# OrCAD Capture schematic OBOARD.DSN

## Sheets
1 core: size B
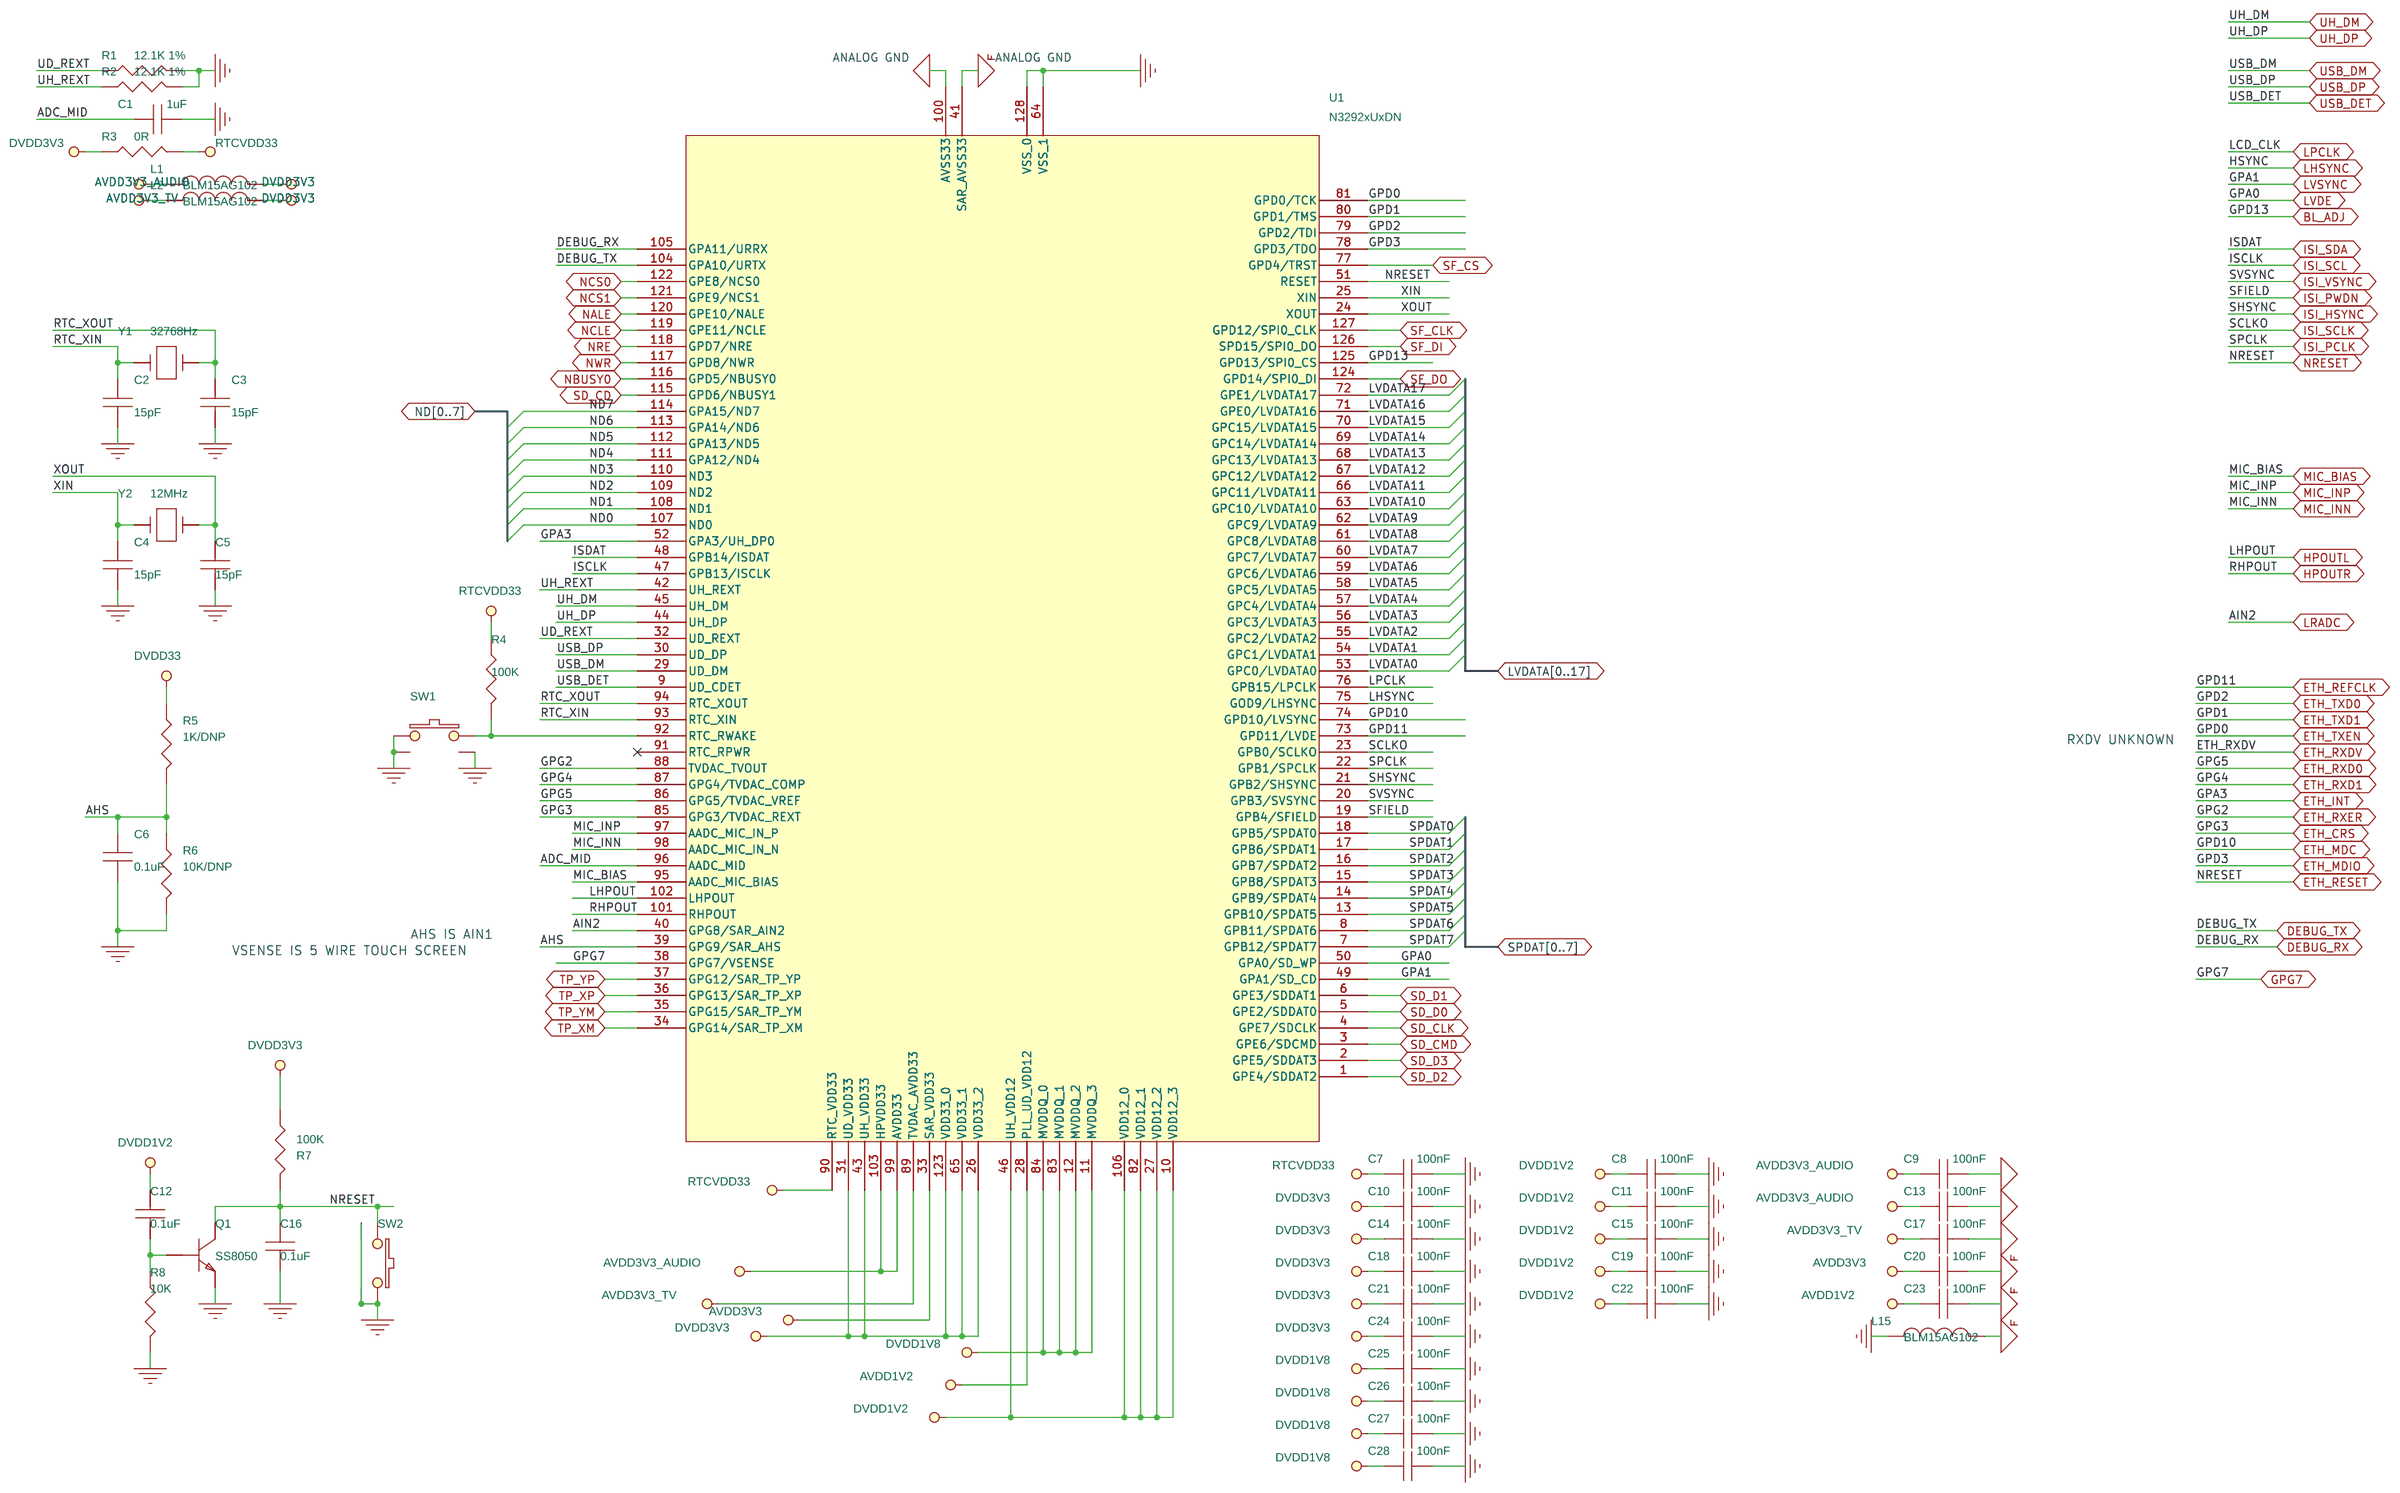
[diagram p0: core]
2 flash: size A
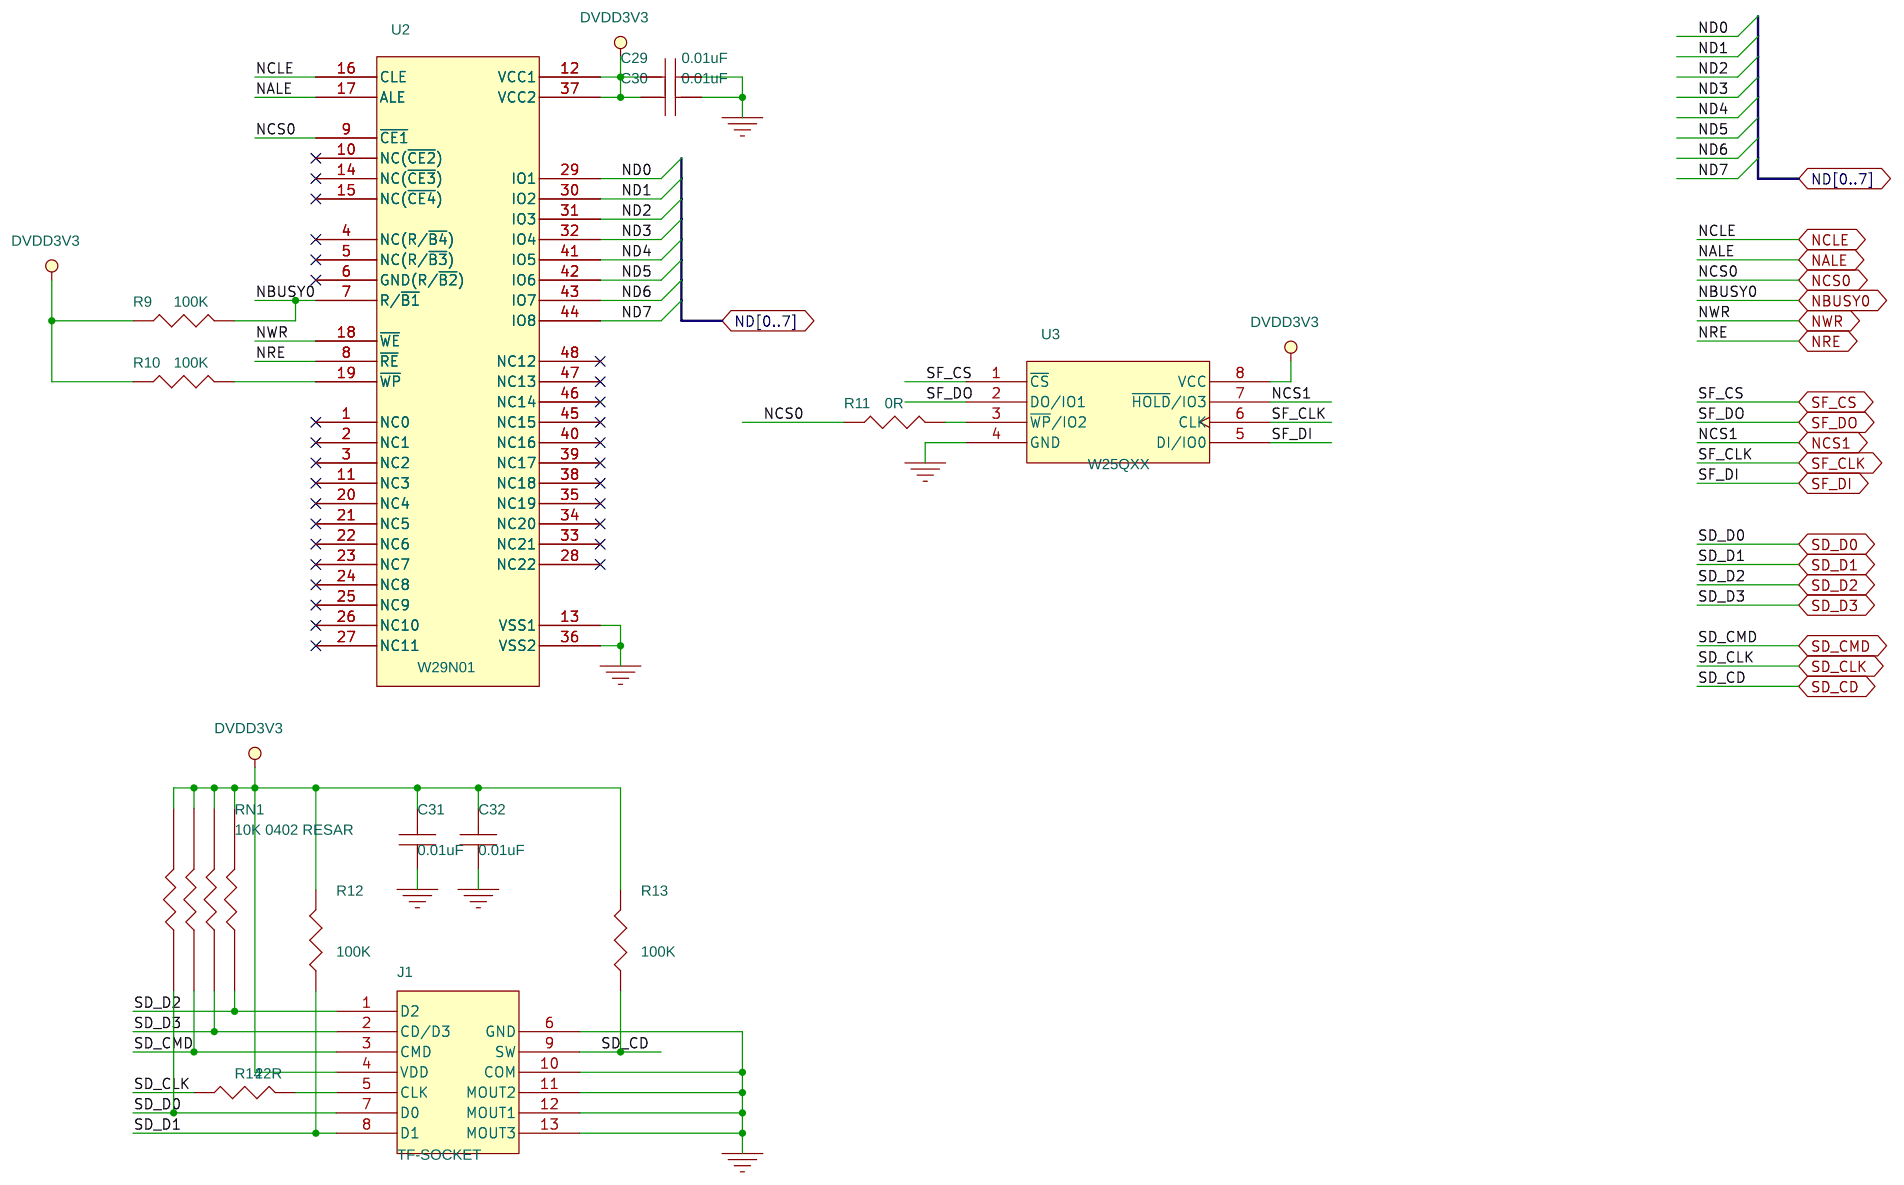
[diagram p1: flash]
3 lcd&isi: size A
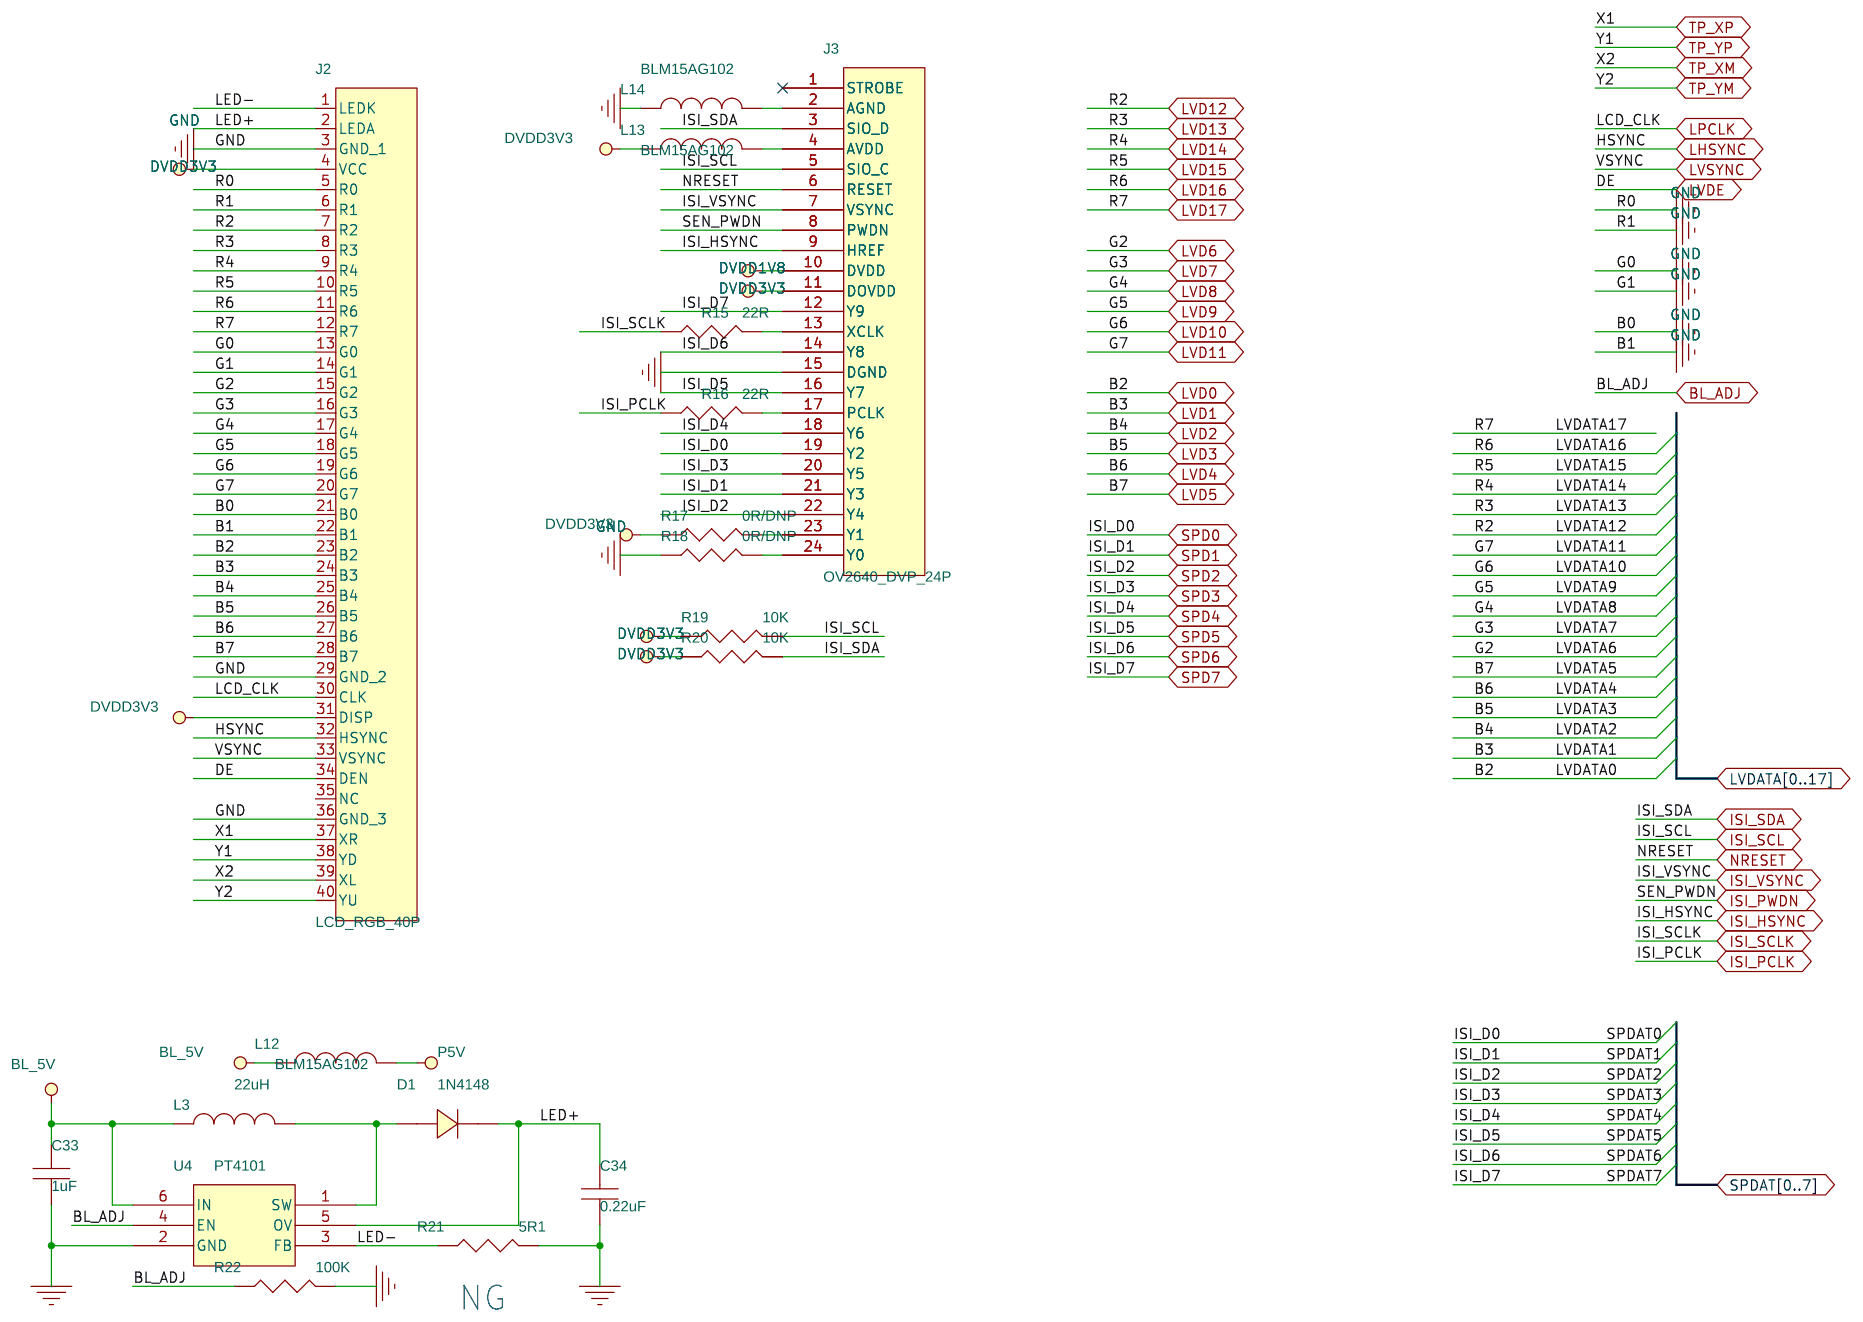
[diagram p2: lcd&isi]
4 misc: size A
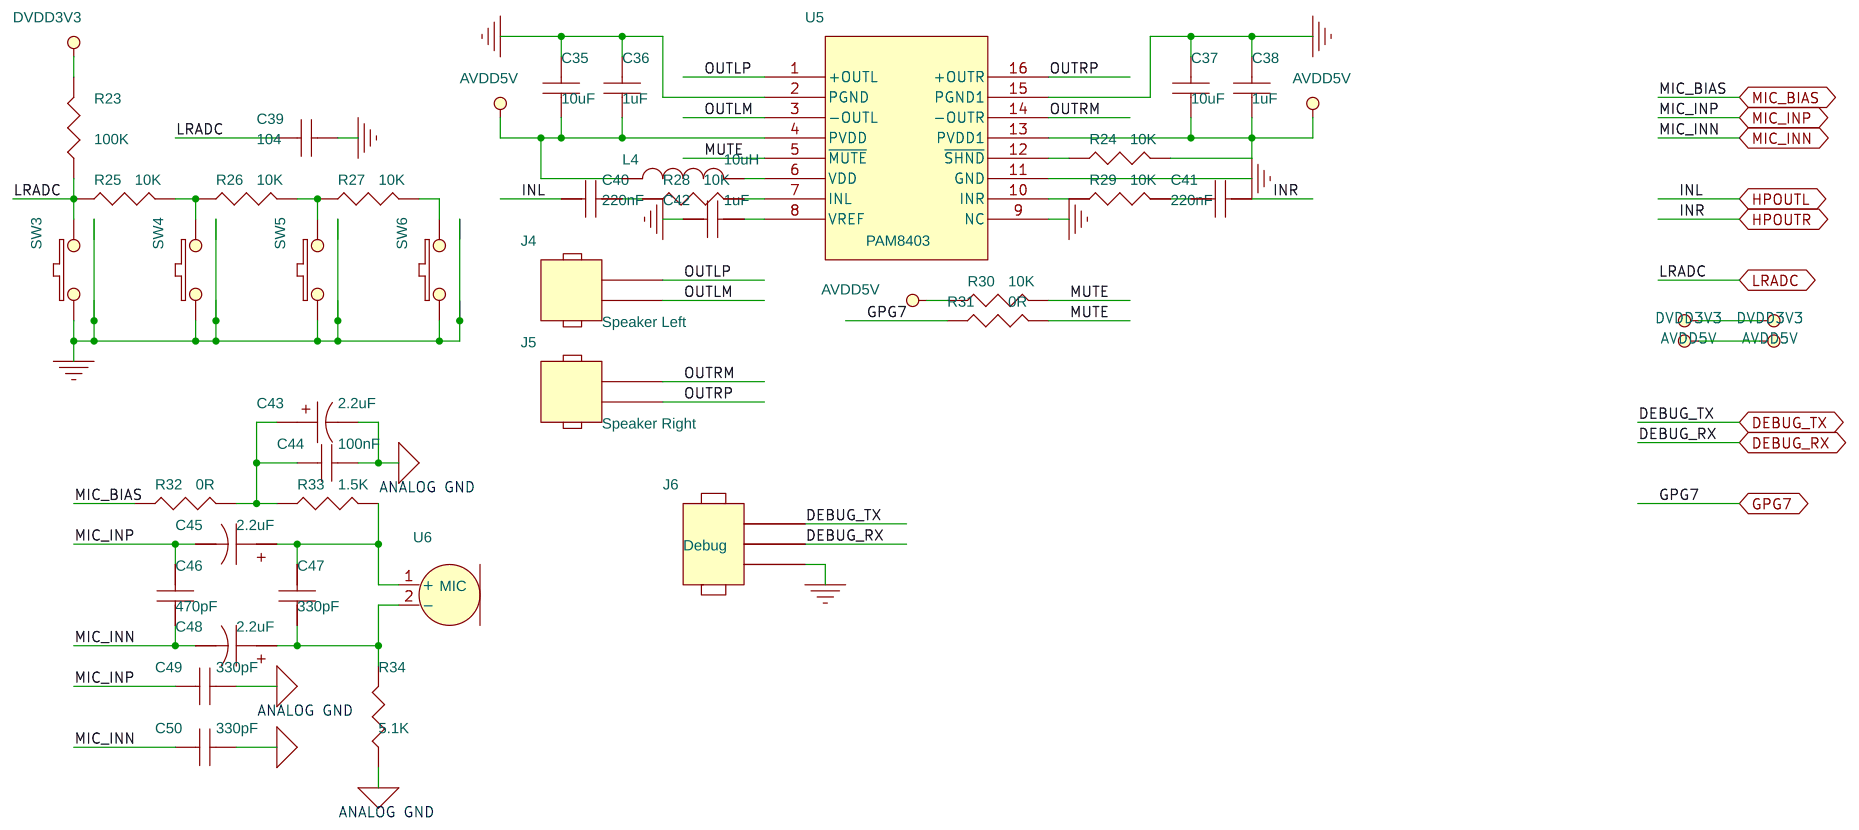
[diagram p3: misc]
5 net: size A
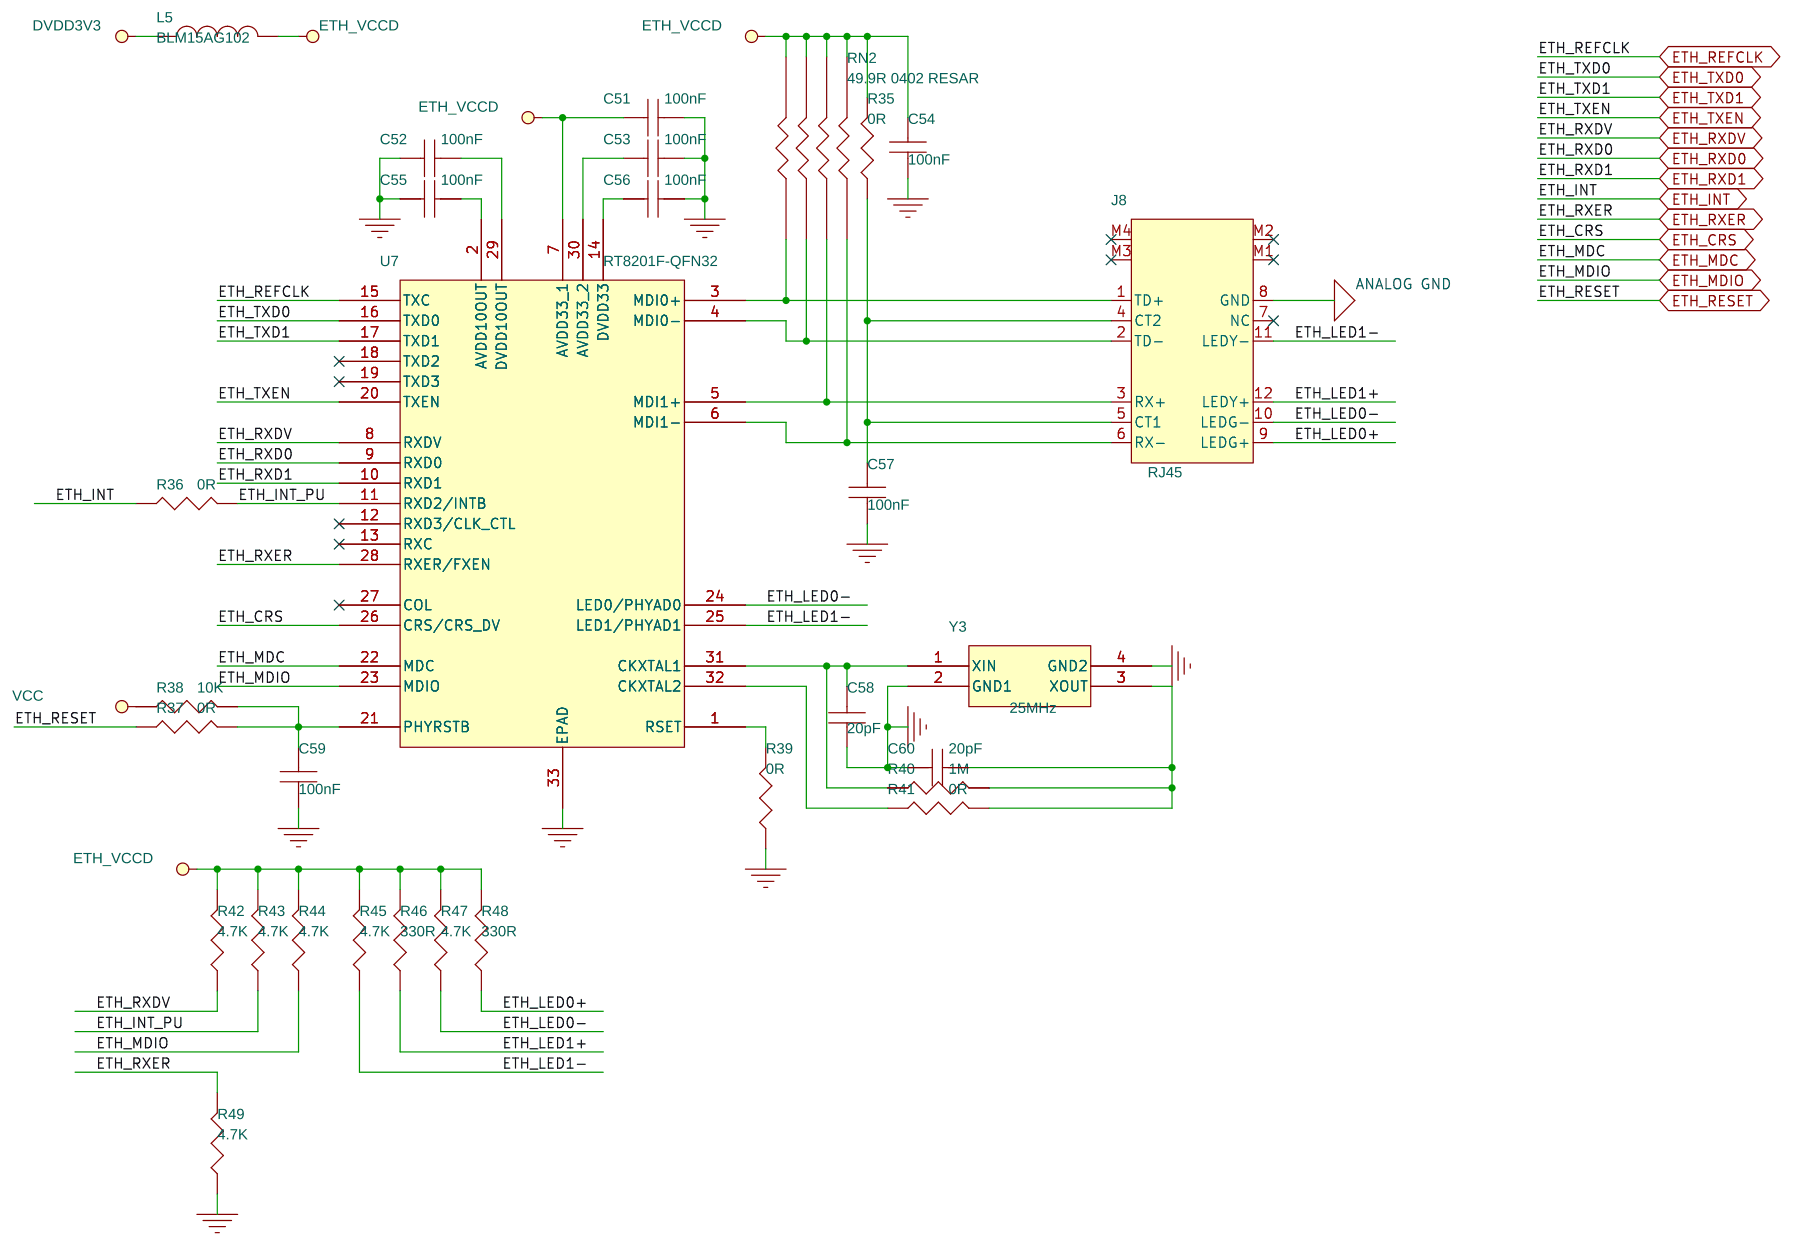
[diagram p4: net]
6 power: size A
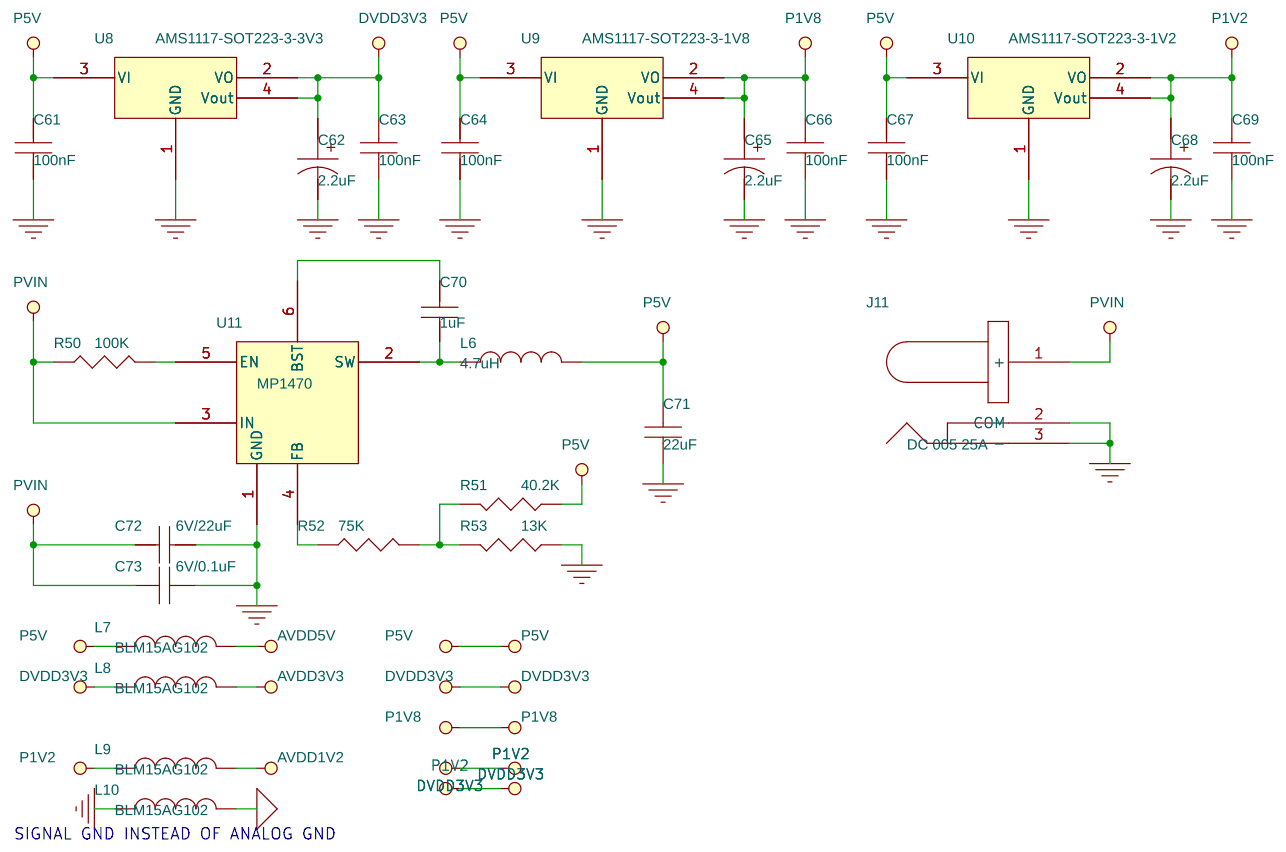
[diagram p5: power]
7 usb: size A
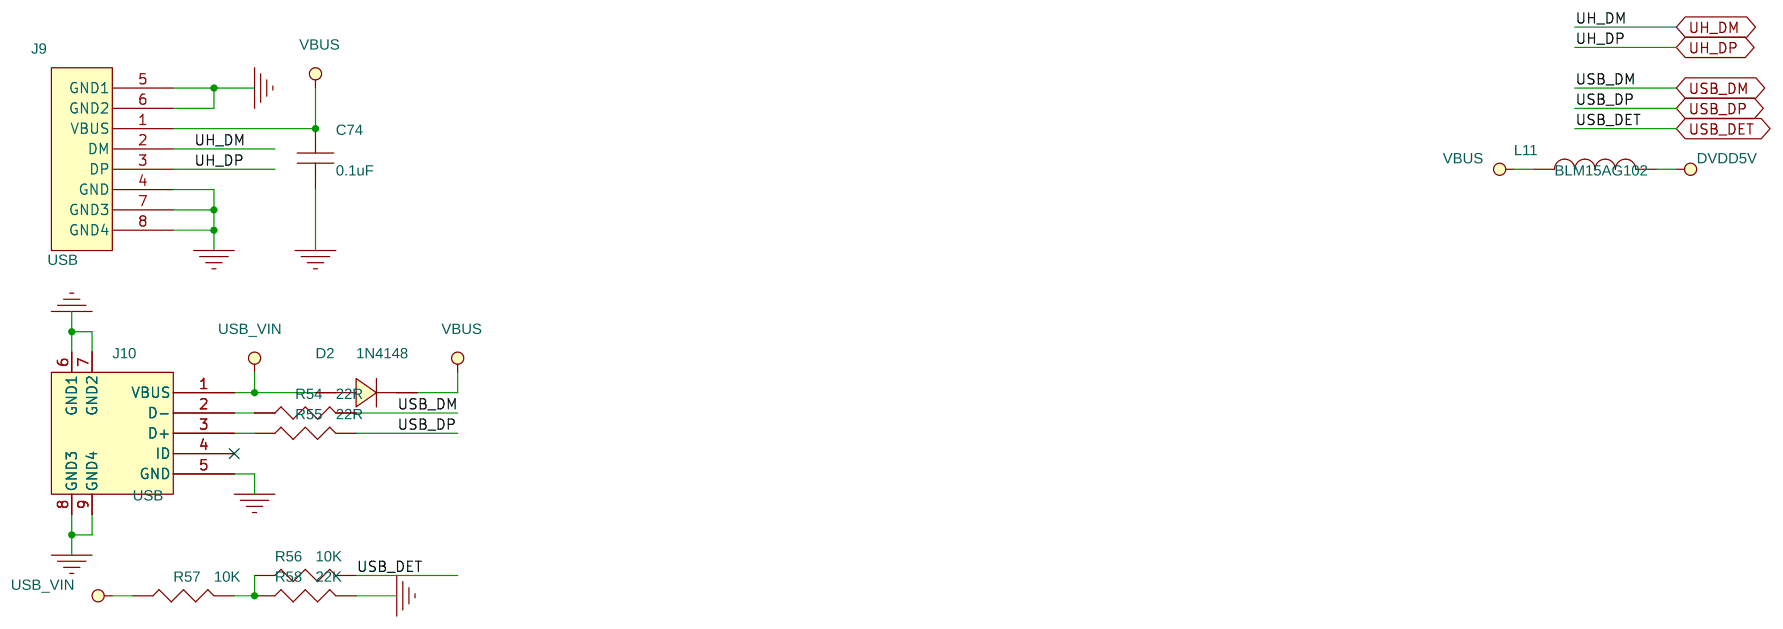
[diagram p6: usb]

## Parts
sheet core
C1  1uF  [cap0402]
C2  15pF  [cap0603]
C3  15pF  [cap0603]
C4  15pF  [cap0603]
C5  15pF  [cap0603]
C6  0.1uF  [cap0402]
C7  100nF  [cap0402]
C8  100nF  [cap0402]
C9  100nF  [cap0402]
C10  100nF  [cap0402]
C11  100nF  [cap0402]
C12  0.1uF  [cap0402]
C13  100nF  [cap0402]
C14  100nF  [cap0402]
C15  100nF  [cap0402]
C16  0.1uF  [cap0402]
C17  100nF  [cap0402]
C18  100nF  [cap0402]
C19  100nF  [cap0402]
C20  100nF  [cap0402]
C21  100nF  [cap0402]
C22  100nF  [cap0402]
C23  100nF  [cap0402]
C24  100nF  [cap0402]
C25  100nF  [cap0402]
C26  100nF  [cap0402]
C27  100nF  [cap0402]
C28  100nF  [cap0402]
L1  BLM15AG102  [BLM15AG221SN1D]
L2  BLM15AG102  [BLM15AG221SN1D]
L15  BLM15AG102  [BLM15AG221SN1D]
Q1  SS8050  [sot23]
R1  12.1K 1%  [res0402]
R2  12.1K 1%  [res0402]
R3  0R  [res0402]
R4  100K  [res0603]
R5  1K/DNP  [res0402]
R6  10K/DNP  [res0402]
R7  100K  [res0402]
R8  10K  [res0402]
SW1  TS_018-4.55x3.5x1.8  [TS_018-4p55x3p5x1p8]
SW2  TS_018-4.55x3.5x1.8  [TS_018-4p55x3p5x1p8]
U1  N3292xUxDN  [N3292xUxDN-LQFP128]
Y1  32768Hz  [CRYSTAL-3215]
Y2  12MHz  [CRYSTAL-3215]
sheet flash
C29  0.01uF  [cap0402]
C30  0.01uF  [cap0402]
C31  0.01uF  [cap0402]
C32  0.01uF  [cap0402]
J1  TF-SOCKET  [TF-SOCKET]
R9  100K  [res0603]
R10  100K  [res0603]
R11  0R  [res0402]
R12  100K  [res0402]
R13  100K  [res0402]
R14  22R  [res0402]
RN1  10K 0402 RESAR  [RN4D02_0402]
U2  W29N01  [W290xHVSINA-TSOP48]
U3  W25QXX  [W25QXX_SOP8_208mil]
sheet lcd&isi
C33  1uF  [cap0603]
C34  0.22uF  [cap0603]
D1  1N4148  [1N4148-SOD323]
J2  LCD_RGB_40P  [FPC-40]
J3  OV2640_DVP_24P  [FPC-24]
L3  22uH  [MLF2012]
L12  BLM15AG102  [BLM15AG221SN1D]
L13  BLM15AG102  [BLM15AG221SN1D]
L14  BLM15AG102  [BLM15AG221SN1D]
R15  22R  [res0402]
R16  22R  [res0402]
R17  0R/DNP  [res0402]
R18  0R/DNP  [res0402]
R19  10K  [res0603]
R20  10K  [res0603]
R21  5R1  [res0603]
R22  100K  [res0603]
U4  PT4101  [pt4101-sot23-6]
sheet misc
C35  10uF  [cap0603]
C36  1uF  [cap0603]
C37  10uF  [cap0603]
C38  1uF  [cap0603]
C39  104  [cap0402]
C40  220nF  [cap0603]
C41  220nF  [cap0603]
C42  1uF  [cap0603]
C43  2.2uF  [CAP3216]
C44  100nF  [cap0402]
C45  2.2uF  [CAP0402]
C46  470pF  [cap0402]
C47  330pF  [cap0402]
C48  2.2uF  [CAP0402]
C49  330pF  [cap0402]
C50  330pF  [cap0402]
J4  Speaker Left  [Header1x2_2_54]
J5  Speaker Right  [Header1x2_2_54]
J6  Debug  [Header1x3_2_54]
L4  10uH  [BLM15AG221SN1D]
R23  100K  [res0603]
R24  10K  [res0603]
R25  10K  [res0603]
R26  10K  [res0603]
R27  10K  [res0603]
R28  10K  [res0603]
R29  10K  [res0603]
R30  10K  [res0603]
R31  0R  [res0402]
R32  0R  [res0402]
R33  1.5K  [res0603]
R34  5.1K  [res0603]
SW3  TS_018-4.55x3.5x1.8  [TS_018-4p55x3p5x1p8]
SW4  TS_018-4.55x3.5x1.8  [TS_018-4p55x3p5x1p8]
SW5  TS_018-4.55x3.5x1.8  [TS_018-4p55x3p5x1p8]
SW6  TS_018-4.55x3.5x1.8  [TS_018-4p55x3p5x1p8]
U5  PAM8403  [PAM8403-SOP16]
U6  MIC  [GMI4015-MIC]
sheet net
C51  100nF  [cap0402]
C52  100nF  [cap0402]
C53  100nF  [cap0402]
C54  100nF  [cap0402]
C55  100nF  [cap0402]
C56  100nF  [cap0402]
C57  100nF  [cap0402]
C58  20pF  [cap0402]
C59  100nF  [cap0402]
C60  20pF  [cap0402]
J8  RJ45  [RJ45_13F-64GYDP2NL]
L5  BLM15AG102  [BLM15AG221SN1D]
R35  0R  [res0402]
R36  0R  [res0402]
R37  0R  [res0402]
R38  10K  [res0402]
R39  0R  [res0402]
R40  1M  [res0402]
R41  0R  [res0402]
R42  4.7K  [res0402]
R43  4.7K  [res0402]
R44  4.7K  [res0402]
R45  4.7K  [res0402]
R46  330R  [res0402]
R47  4.7K  [res0402]
R48  330R  [res0402]
R49  4.7K  [res0402]
RN2  49.9R 0402 RESAR  [RN4D02_0402]
U7  RT8201F-QFN32  [RTL8201-QFN32]
Y3  25MHz  [YSX321SL-3_2x2_5x0_8]
sheet power
C61  100nF  [cap0402]
C62  2.2uF  [cap0603]
C63  100nF  [cap0402]
C64  100nF  [cap0402]
C65  2.2uF  [cap0603]
C66  100nF  [cap0402]
C67  100nF  [cap0402]
C68  2.2uF  [cap0603]
C69  100nF  [cap0402]
C70  1uF  [cap0603]
C71  22uF  [cap3216]
C72  6V/22uF  [cap3216]
C73  6V/0.1uF  [cap0603]
J11  DC 005 25A  [DC_005_25A]
L6  4.7uH  [MLF2012]
L7  BLM15AG102  [BLM15AG221SN1D]
L8  BLM15AG102  [BLM15AG221SN1D]
L9  BLM15AG102  [BLM15AG221SN1D]
L10  BLM15AG102  [BLM15AG221SN1D]
R50  100K  [res0603]
R51  40.2K  [res0603]
R52  75K  [res0603]
R53  13K  [res0603]
U8  AMS1117-SOT223-3-3V3  [AMS1117-SOT223-3]
U9  AMS1117-SOT223-3-1V8  [AMS1117-SOT223-3]
U10  AMS1117-SOT223-3-1V2  [AMS1117-SOT223-3]
U11  MP1470  [MP1470-TSOT23-6]
sheet usb
C74  0.1uF  [cap0402]
D2  1N4148  [1N4148-SOD323]
J9  USB  [USB-AF]
J10  USB  [MicroUSB]
L11  BLM15AG102  [BLM15AG221SN1D]
R54  22R  [res0603]
R55  22R  [res0603]
R56  10K  [res0603]
R57  10K  [res0603]
R58  22K  [res0603]

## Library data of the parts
C1-C32 C51-C57 C59 C61 C63 C64 C66 C67 C69 C74 = CAP_NP
L1 L2 L5 L7-L15 = INDUCTOR
Q1 = BPW37_TO
R1-R20 R35-R39 R54-R58 = RESISTOR
SW1-SW6 = TS_018-4.55x3.5x1.8
U1 = N3292xUxDN
Y1 Y2 = CRYSTAL
J1 = TF-SOCKET
RN1 RN2 = RESAR_IS_4_SM
U2 = W29N01_GVSCAA
U3 = W25QXX
C33-C42 C44 C46 C47 C49 C50 C58 C60 C70-C73 = CAPACITOR_NON-POL
D1 D2 = DIODE
J2 = LCD_RGB_40P
J3 = OV2640_DVP_24P
L3 L4 L6 = INDUCTOR_SM
R21-R34 R40-R53 = RESISTOR_SM
U4 = PT4101
C43 C45 C48 C62 C65 C68 = CAP_POL
J4 J5 = HEADER_2
J6 = HEADER_3
U5 = PAM8403
U6 = MIC
J8 = RJ45
U7 = RT8201F-QFN32
Y3 = YSX321SL
J11 = DC005-25A
U8-U10 = ASM1117-SOT223-3
U11 = MP1470
J9 = USB_AF
J10 = MICROUSB

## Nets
AVDD1V2: C23.1 L9.1 U1.28(PLL_UD_VDD12)
AVDD3V3: C20.1 L8.1 U1.33(SAR_VDD33)
AVDD3V3_AUDIO: C9.1 C13.1 L1.2 U1.99(AVDD33) U1.103(HPVDD33)
AVDD3V3_TV: C17.1 L2.2 U1.89(TVDAC_AVDD33)
AVDD5V: C35.1 C36.1 C37.1 C38.1 L4.1 L7.1 R24.2 R30.1 U5.4(PVDD) U5.13(PVDD1)
DVDD1V2: C8.1 C11.1 C12.1 C15.1 C19.1 C22.1 C68.1 C69.1 L9.2 U1.10(VDD12_3) U1.27(VDD12_2) U1.46(UH_VDD12) U1.82(VDD12_1) U1.106(VDD12_0) U10.2(VO) U10.4(Vout)
DVDD1V8: C25.1 C26.1 C27.1 C28.1 C65.1 C66.1 J3.10(DVDD) U1.11(MVDDQ_3) U1.12(MVDDQ_2) U1.83(MVDDQ_1) U1.84(MVDDQ_0) U9.2(VO) U9.4(Vout)
DVDD5V: C61.1 C64.1 C67.1 C71.1 L6.2 L7.2 L11.1 L12.1 R51.1 U8.3(VI) U9.3(VI) U10.3(VI)
DVDD33: C10.1 C14.1 C18.1 C21.1 C24.1 C29.1 C30.1 C31.2 C32.2 C62.1 C63.1 J1.4(VDD) J2.4(VCC) J2.31(DISP) J3.11(DOVDD) L1.1 L2.1 L5.1 L8.2 L13.2 R3.1 R5.1 R7.2 R9.1 R10.1 R12.2 R13.2 R17.1 R19.1 R20.1 R23.2 RN1.5 RN1.6 RN1.7 RN1.8 U1.26(VDD33_2) U1.31(UD_VDD33) U1.43(UH_VDD33) U1.65(VDD33_1) U1.123(VDD33_0) U2.12(VCC1) U2.37(VCC2) U3.8(VCC) U8.2(VO) U8.4(Vout)
GND: C1.2 C2.2 C3.2 C4.2 C5.2 C6.2 C7.2 C8.2 C10.2 C11.2 C14.2 C15.2 C16.2 C18.2 C19.2 C21.2 C22.2 C24.2 C25.2 C26.2 C27.2 C28.2 C29.2 C30.2 C31.1 C32.1 C33.2 C34.2 C35.2 C36.2 C37.2 C38.2 C39.2 C42.1 C51.2 C52.1 C53.2 C54.2 C55.1 C56.2 C57.2 C58.1 C59.2 C60.1 C61.2 C62.2 C63.2 C64.2 C65.2 C66.2 C67.2 C68.2 C69.2 C71.2 C72.2 C73.2 C74.2 J1.6(GND) J1.10(COM) J1.11(MOUT2) J1.12(MOUT1) J1.13(MOUT3) J2.3(GND_1) J2.5(R0) J2.6(R1) J2.13(G0) J2.14(G1) J2.21(B0) J2.22(B1) J2.29(GND_2) J2.36(GND_3) J3.15(DGND) J6.3 J9.4(GND) J9.5(GND1) J9.6(GND2) J9.7(GND3) J9.8(GND4) J10.5(GND) J10.6(GND1) J10.7(GND2) J10.8(GND3) J10.9(GND4) J11.2(COM) J11.3(-) L10.2 L14.2 L15.2 Q1.1(EMITTER) R1.2 R2.2 R6.2 R8.2 R18.1 R21.2 R22.2 R39.1 R49.1 R53.1 R58.2 SW1.1 SW1.2 SW1.3 SW2.1 SW2.2 SW2.3 SW3.1 SW3.2 SW3.3 SW4.1 SW4.2 SW4.3 SW5.1 SW5.2 SW5.3 SW6.1 SW6.2 SW6.3 U1.64(VSS_1) U1.128(VSS_0) U2.13(VSS1) U2.36(VSS2) U3.4(GND) U4.2(GND) U5.2(PGND) U5.9(NC) U5.11(GND) U5.15(PGND1) U7.33(EPAD) U8.1(GND) U9.1(GND) U10.1(GND) U11.1(GND) Y3.2(GND1) Y3.4(GND2)
GND_FIELD SIGNAL: C20.2 C23.2 L15.1 U1.41(SAR_AVSS33)
GND_SIGNAL: C9.2 C13.2 C17.2 C43.2 C44.2 C49.2 C50.2 J8.8(GND) L10.1 R34.1 U1.100(AVSS33)
PVIN: C72.1 C73.1 J11.1(+) R50.1 U11.3(IN)
VBUS: C74.1 D2.1(K) J9.1(VBUS) L11.2
ADC_MID: C1.1 U1.96(AADC_MID)
AHS: C6.1 R5.2 R6.1 U1.39(GPG9/SAR_AHS)
BL_5V: C33.1 L3.1 L12.2 U4.6(IN)
BL_ADJ: R22.1 U1.125(GPD13/SPI0_CS) U4.4(EN)
DEBUG_RX: J6.2 U1.105(GPA11/URRX)
DEBUG_TX: J6.1 U1.104(GPA10/URTX)
ETH_CRS: U1.85(GPG3/TVDAC_REXT) U7.26(CRS/CRS_DV)
ETH_INT: R36.1 U1.52(GPA3/UH_DP0)
ETH_INT_PU: R36.2 R43.1 U7.11(RXD2/INTB)
ETH_LED0+: J8.9(LEDG+) R48.1
ETH_LED0-: J8.10(LEDG-) R47.1 U7.24(LED0/PHYAD0)
ETH_LED1+: J8.12(LEDY+) R46.1
ETH_LED1-: J8.11(LEDY-) R45.1 U7.25(LED1/PHYAD1)
ETH_MDC: U1.74(GPD10/LVSYNC) U7.22(MDC)
ETH_MDIO: R44.1 U1.78(GPD3/TDO) U7.23(MDIO)
ETH_REFCLK: U1.73(GPD11/LVDE) U7.15(TXC)
ETH_RESET: C16.1 J3.6(RESET) Q1.3(COLLECTOR) R7.1 R37.1 SW2.4 U1.51(RESET)
ETH_RXD0: U1.86(GPG5/TVDAC_VREF) U7.9(RXD0)
ETH_RXD1: U1.87(GPG4/TVDAC_COMP) U7.10(RXD1)
ETH_RXDV: R42.1 U7.8(RXDV)
ETH_RXER: R49.2 U1.88(TVDAC_TVOUT) U7.28(RXER/FXEN)
ETH_TXD0: U1.79(GPD2/TDI) U7.16(TXD0)
ETH_TXD1: U1.80(GPD1/TMS) U7.17(TXD1)
ETH_TXEN: U1.81(GPD0/TCK) U7.20(TXEN)
ETH_VCCD: C51.1 C54.1 L5.2 R35.2 R38.1 R42.2 R43.2 R44.2 R45.2 R46.2 R47.2 R48.2 RN2.5 RN2.6 RN2.7 RN2.8 U7.7(AVDD33_1)
GPG7: R31.1 U1.38(GPG7/VSENSE)
HPOUTL: C40.1 U1.102(LHPOUT)
HPOUTR: C41.2 U1.101(RHPOUT)
ISI_HSYNC: J3.9(HREF) U1.21(GPB2/SHSYNC)
ISI_PCLK: R16.1 U1.22(GPB1/SPCLK)
ISI_PWDN: J3.8(PWDN) U1.19(GPB4/SFIELD)
ISI_SCL: J3.5(SIO_C) R19.2 U1.47(GPB13/ISCLK)
ISI_SCLK: R15.1 U1.23(GPB0/SCLKO)
ISI_SDA: J3.3(SIO_D) R20.2 U1.48(GPB14/ISDAT)
ISI_VSYNC: J3.7(VSYNC) U1.20(GPB3/SVSYNC)
LED+: C34.1 D1.1(K) J2.2(LEDA) U4.5(OV)
LED-: J2.1(LEDK) R21.1 U4.3(FB)
LHSYNC: J2.32(HSYNC) U1.75(GOD9/LHSYNC)
LPCLK: J2.30(CLK) U1.76(GPB15/LPCLK)
LRADC: C39.1 R23.1 R25.1 SW3.4 U1.40(GPG8/SAR_AIN2)
LVD0: J2.23(B2) U1.53(GPC0/LVDATA0)
LVD1: J2.24(B3) U1.54(GPC1/LVDATA1)
LVD2: J2.25(B4) U1.55(GPC2/LVDATA2)
LVD3: J2.26(B5) U1.56(GPC3/LVDATA3)
LVD4: J2.27(B6) U1.57(GPC4/LVDATA4)
LVD5: J2.28(B7) U1.58(GPC5/LVDATA5)
LVD6: J2.15(G2) U1.59(GPC6/LVDATA6)
LVD7: J2.16(G3) U1.60(GPC7/LVDATA7)
LVD8: J2.17(G4) U1.61(GPC8/LVDATA8)
LVD9: J2.18(G5) U1.62(GPC9/LVDATA9)
LVD10: J2.19(G6) U1.63(GPC10/LVDATA10)
LVD11: J2.20(G7) U1.66(GPC11/LVDATA11)
LVD12: J2.7(R2) U1.67(GPC12/LVDATA12)
LVD13: J2.8(R3) U1.68(GPC13/LVDATA13)
LVD14: J2.9(R4) U1.69(GPC14/LVDATA14)
LVD15: J2.10(R5) U1.70(GPC15/LVDATA15)
LVD16: J2.11(R6) U1.71(GPE0/LVDATA16)
LVD17: J2.12(R7) U1.72(GPE1/LVDATA17)
LVDE: J2.34(DEN) U1.50(GPA0/SD_WP)
LVSYNC: J2.33(VSYNC) U1.49(GPA1/SD_CD)
MIC_BIAS: R32.1 U1.95(AADC_MIC_BIAS)
MIC_INN: C46.1 C48.2 C50.1 U1.98(AADC_MIC_IN_N)
MIC_INP: C45.2 C46.2 C49.1 U1.97(AADC_MIC_IN_P)
MUTE: R30.2 R31.2 U5.5(~{MUTE})
NALE: U1.120(GPE10/NALE) U2.17(ALE)
NBUSY0: R9.2 U1.116(GPD5/NBUSY0) U2.7(R/~{B1})
NCLE: U1.119(GPE11/NCLE) U2.16(CLE)
NCS0: R11.1 U1.122(GPE8/NCS0) U2.9(~{CE1})
NCS1: U1.121(GPE9/NCS1) U3.7(~{HOLD}/IO3)
ND0: U1.107(ND0) U2.29(IO1)
ND1: U1.108(ND1) U2.30(IO2)
ND2: U1.109(ND2) U2.31(IO3)
ND3: U1.110(ND3) U2.32(IO4)
ND4: U1.111(GPA12/ND4) U2.41(IO5)
ND5: U1.112(GPA13/ND5) U2.42(IO6)
ND6: U1.113(GPA14/ND6) U2.43(IO7)
ND7: U1.114(GPA15/ND7) U2.44(IO8)
NRE: U1.118(GPD7/NRE) U2.8(~{RE})
NWR: U1.117(GPD8/NWR) U2.18(~{WE})
OUTLM: J4.2 U5.3(-OUTL)
OUTLP: J4.1 U5.1(+OUTL)
OUTRM: J5.1 U5.14(-OUTR)
OUTRP: J5.2 U5.16(+OUTR)
RTC_XIN: C2.1 U1.93(RTC_XIN) Y1.1
RTC_XOUT: C3.1 U1.94(RTC_XOUT) Y1.2
RTCVDD33: C7.1 R3.2 R4.1 U1.90(RTC_VDD33)
SD_CD: J1.9(SW) R13.1 U1.115(GPD6/NBUSY1)
SD_CLK: R14.1 U1.4(GPE7/SDCLK)
SD_CMD: J1.3(CMD) RN1.2 U1.3(GPE6/SDCMD)
SD_D0: J1.7(D0) RN1.1 U1.5(GPE2/SDDAT0)
SD_D1: J1.8(D1) R12.1 U1.6(GPE3/SDDAT1)
SD_D2: J1.1(D2) RN1.4 U1.1(GPE4/SDDAT2)
SD_D3: J1.2(CD/D3) RN1.3 U1.2(GPE5/SDDAT3)
SF_CLK: U1.127(GPD12/SPI0_CLK) U3.6(CLK)
SF_CS: U1.77(GPD4/TRST) U3.1(~{CS})
SF_DI: U1.126(SPD15/SPI0_DO) U3.5(DI/IO0)
SF_DO: U1.124(GPD14/SPI0_DI) U3.2(DO/IO1)
SPD0: J3.19(Y2) U1.18(GPB5/SPDAT0)
SPD1: J3.21(Y3) U1.17(GPB6/SPDAT1)
SPD2: J3.22(Y4) U1.16(GPB7/SPDAT2)
SPD3: J3.20(Y5) U1.15(GPB8/SPDAT3)
SPD4: J3.18(Y6) U1.14(GPB9/SPDAT4)
SPD5: J3.16(Y7) U1.13(GPB10/SPDAT5)
SPD6: J3.14(Y8) U1.8(GPB11/SPDAT6)
SPD7: J3.12(Y9) U1.7(GPB12/SPDAT7)
TP_XM: J2.39(XL) U1.34(GPG14/SAR_TP_XM)
TP_XP: J2.37(XR) U1.36(GPG13/SAR_TP_XP)
TP_YM: J2.40(YU) U1.35(GPG15/SAR_TP_YM)
TP_YP: J2.38(YD) U1.37(GPG12/SAR_TP_YP)
UD_REXT: R1.1 U1.32(UD_REXT)
UH_DM: J9.2(DM) U1.45(UH_DM)
UH_DP: J9.3(DP) U1.44(UH_DP)
UH_REXT: R2.1 U1.42(UH_REXT)
USB_DET: R56.2 U1.9(UD_CDET)
USB_DM: R54.2 U1.29(UD_DM)
USB_DP: R55.2 U1.30(UD_DP)
USB_VIN: D2.2(A) J10.1(VBUS) R57.1
XIN: C4.1 U1.25(XIN) Y2.1
XOUT: C5.1 U1.24(XOUT) Y2.2
N04211: R10.2 U2.19(~{WP})
N06862: J1.5(CLK) R14.2
N09654: R11.2 U3.3(~{WP}/IO2)
N15646006: J3.13(XCLK) R15.2
N15646070: J3.17(PCLK) R16.2
N15663479: C52.2 U7.29(DVDD10OUT)
N15663486: C55.2 U7.2(AVDD10OUT)
N15663493: C56.1 U7.14(DVDD33)
N15663500: C53.1 U7.30(AVDD33_2)
N15663575: C59.1 R37.2 R38.2 U7.21(PHYRSTB)
N15663676: R39.2 U7.1(RSET)
N15663702: R41.1 U7.32(CKXTAL2)
N15664512: C60.2 R40.2 R41.2 Y3.3(XOUT)
N15664809: C58.2 R40.1 U7.31(CKXTAL1) Y3.1(XIN)
N15668493: J8.1(TD+) RN2.1 U7.3(MDI0+)
N15668513: J8.2(TD-) RN2.2 U7.4(MDI0-)
N15668525: J8.3(RX+) RN2.3 U7.5(MDI1+)
N15668529: J8.6(RX-) RN2.4 U7.6(MDI1-)
N15668719: C57.1 J8.4(CT2) J8.5(CT1) R35.1
N15674337: R25.2 R26.1 SW4.4
N15674345: R26.2 R27.1 SW5.4
N15674353: R27.2 SW6.4
N15676008: R24.1 U5.12(~{SHND})
N15676062: L4.2 U5.6(VDD)
N15676114: C40.2 R28.1
N15676138: R28.2 U5.7(INL)
N15676142: R29.1 U5.10(INR)
N15676150: C41.1 R29.2
N15676164: C42.2 U5.8(VREF)
N15687660: C70.2 U11.6(BST)
N15687760: C70.1 L6.1 U11.2(SW)
N15687792: R50.2 U11.5(EN)
N15687876: R51.2 R52.2 R53.2
N15687912: R52.1 U11.4(FB)
N15691835: D1.2(A) L3.2 U4.1(SW)
N15705525: C43.1 C44.1 R32.2 R33.1
N15705529: C45.1 C47.2 R33.2 U6.1(+)
N15705631: C47.1 C48.1 R34.2 U6.2(-)
N15714383: J10.2(D-) R54.1
N15714387: J10.3(D+) R55.1
N15739714: R4.2 SW1.4 U1.92(RTC_RWAKE)
N15742573: C12.2 Q1.2(BASE) R8.1
N15750041: R56.1 R57.2 R58.1
N15763803: J3.24(Y0) R18.2
N15763807: J3.23(Y1) R17.2
N15841040: J3.4(AVDD) L13.1
N15841559: J3.2(AGND) L14.1

Not connected (* = marked no-connect by the designer): J2 35(NC); J3 1(STROBE)*; J8 7(NC)* M1* M2* M3* M4*; J10 4(ID)*; U1 91(RTC_RPWR)*; U2 1(NC0)* 2(NC1)* 3(NC2)* 4(NC(R/~{B4}))* 5(NC(R/~{B3}))* 6(GND(R/~{B2}))* 10(NC(~{CE2}))* 11(NC3)* 14(NC(~{CE3}))* 15(NC(~{CE4}))* 20(NC4)* 21(NC5)* 22(NC6)* 23(NC7)* 24(NC8)* 25(NC9)* 26(NC10)* 27(NC11)* 28(NC22)* 33(NC21)* 34(NC20)* 35(NC19)* 38(NC18)* 39(NC17)* 40(NC16)* 45(NC15)* 46(NC14)* 47(NC13)* 48(NC12)*; U7 12(RXD3/CLK_CTL)* 13(RXC)* 18(TXD2)* 19(TXD3)* 27(COL)*

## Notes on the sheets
sheet 1
- ANALOG GND
- ANALOG GND
- RXDV UNKNOWN
- AHS IS AIN1
- VSENSE IS 5 WIRE TOUCH SCREEN
sheet 3
- NG
sheet 4
- ANALOG GND
- ANALOG GND
- ANALOG GND
sheet 5
- ANALOG GND
sheet 6
- SIGNAL GND INSTEAD OF ANALOG GND
